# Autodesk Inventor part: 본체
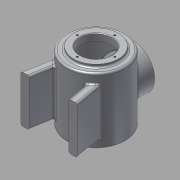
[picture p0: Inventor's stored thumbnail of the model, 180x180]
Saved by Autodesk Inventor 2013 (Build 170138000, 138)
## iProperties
Created: 2015-01
Part Number: 본체
Material: 알루미늄 6061
Document SubType Name: Modeling
Designer: Administrator
Density: 2.71 g/cm^3
Mass: 1058.71 g
Surface Area: 1085.54 cm^2
Volume: 390.668 cm^3
Author: Administrator
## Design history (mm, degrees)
sketch "스케치2"
  geometry: C1 r 50 at (0, 0); 1 further point
  constraints: 1 centre point, 1 coincident
  dimensions: "d0" = 100 diameter of C1
extrude "돌출1" new body sketch "스케치2" distance "d1" = 112; taper "d2" = 0 deg
sketch "스케치3"
  geometry: C1 r 38 at (0, 0); 1 further point
  constraints: 1 centre point, 1 coincident
  dimensions: "d3" = 76 diameter of C1
extrude "돌출2" join sketch "스케치3" distance "d4" = 5; taper "d5" = 0 deg
sketch "스케치4"
  geometry: C1 r 38 at (0, 0); 1 further point
  constraints: 1 centre point, 1 coincident
  dimensions: "d6" = 76 diameter of C1
extrude "돌출3" join sketch "스케치4" distance "d7" = 5; taper "d8" = 0 deg
node "작업 평면2"
  node "작업 평면1"
hole "구멍1" diameter "d25" = 54; stored, may be unused: countersink angle "d29" = 90 deg, drill point angle "d31" = 0 deg; dims "d23" = 10, "d24" = 10, "d26" = 6, "d27" = 4, "d28" = 2, "d30" = 13
hole "구멍2" diameter "d34" = 90; stored, may be unused: countersink angle "d38" = 90 deg, drill point angle "d40" = 0 deg; dims "d32" = 10, "d33" = 10, "d35" = 6, "d36" = 4, "d37" = 2, "d39" = 97
hole "구멍3" diameter "d43" = 54; stored, may be unused: countersink angle "d47" = 90 deg, drill point angle "d49" = 0 deg; dims "d41" = 10, "d42" = 10, "d44" = 6, "d45" = 4, "d46" = 2, "d48" = 12
fillet "모깎기1" dims "d50" = 3
chamfer "모따기1" distance "d51" = 1; stored, may be unused: second distance "d52" = 2, angle "d53" = 45 deg
node "작업 평면3"
sketch "스케치6"
  geometry: L1 (38, 117)-(-38, 117) reference; C1 r 38 at (0, 57); 2 further points
  constraints: 1 centre point, 1 midpoint, 1 vertical alignment
  dimensions: "d58" = 76 diameter of C1; "d59" = 60 distance from line of C1.centre L1
extrude "돌출5" join sketch "스케치6" stored distance "d60" = 80; taper "d61" = 0 deg
hole "구멍4" diameter "d64" = 54; stored, may be unused: countersink angle "d68" = 90 deg, drill point angle "d70" = 0 deg; dims "d62" = 10, "d63" = 10, "d65" = 6, "d66" = 4, "d67" = 2, "d69" = 50
sketch "스케치7"
  geometry: C1 r 38 at (0, 0) reference; 2 further points
  constraints: 1 horizontal alignment
  dimensions: "d71" = 32 distance of C1.centre point (-32, 0)
hole "구멍5" sketch "스케치7" at (-32, 0) diameter "d72" = 3.242; stored, may be unused: countersink angle "d76" = 90 deg, drill point angle "d78" = 118 deg; dims "d73" = 8, "d74" = 4, "d75" = 2, "d77" = 10
sketch "스케치8"
  geometry: C1 r 38 at (0, 0) reference; 2 further points
  constraints: 1 vertical alignment
  dimensions: "d82" = 32 distance of point (0, 0) point (0, 32)
hole "구멍6" sketch "스케치8" at (0, 32) diameter "d83" = 3.242; stored, may be unused: countersink angle "d87" = 90 deg, drill point angle "d89" = 118 deg; dims "d84" = 8, "d85" = 4, "d86" = 2, "d88" = 10
node "작업 평면4"
fillet "모깎기2" dims "d93" = 3
node "작업 평면5"
sketch "스케치9"
  geometry: L1 (-6, 30)-(6, 30); L2 (6, 30)-(6, 84); L3 (6, 84)-(-6, 84); L4 (-6, 84)-(-6, 30); L5 (-38, -5)-(38, -5) reference; 2 further points
  constraints: 8 end point, 2 parallel, 1 horizontal, 1 midpoint, 1 perpendicular, 1 vertical alignment
  dimensions: "d98" = 54 distance between parallel lines of L3 L1; "d100" = 12 distance between parallel lines of L4 L2; "d101" = 35 distance between parallel lines of L1 L5
extrude "돌출6" join sketch "스케치9" stored distance "d102" = 80; taper "d103" = 0 deg
sketch "스케치10"
  geometry: L1 (30, -6)-(30, 6) reference; 3 further points
  constraints: 1 horizontal alignment, 1 midpoint, 1 other
  dimensions: "d104" = 27 distance from line of point (57, 0) L1
feature "엠보싱1" sketch "스케치10" dims "d105" = 0.5, "d106" = 0
chamfer "모따기2" distance "d107" = 1; stored, may be unused: second distance "d108" = 2, angle "d109" = 45 deg
fillet "모깎기6" dims "d110" = 3
fillet "모깎기7" dims "d111" = 3
node "작업 평면6"
sketch "스케치11"
  geometry: L1 (-39.336, -30.865)-(-48, -80); L2 (-27.088, -42.026)-(-33.784, -80); L3 (-48, -80)-(-33.784, -80); L4 (0, 0)-(-50, 0); L5 (0, 0)-(0, -50); A1 r 50 centre (0, 0) between (-39.336, -30.865) and (-27.088, -42.026) reference; 1 further point
  constraints: 10 end point, 4 point on circle, 2 parallel, 1 horizontal, 1 perpendicular
  dimensions: "d117" = 80 distance between parallel lines of L3 L4; "d119" = 14 distance between parallel lines of L2 L1; "d120" = 80 deg angle of L2 L3; "d121" = 48 distance from line of L1.end L5
extrude "돌출7" join sketch "스케치11" stored distance "d122" = 80; taper "d123" = 0 deg
fillet "모깎기8" dims "d124" = 3
fillet "모깎기9" dims "d125" = 3
node "솔리드1"
pattern_circular "원형 패턴1" dims angle "d80" = 360 deg
pattern_circular "원형 패턴2" dims angle "d91" = 360 deg
mirror "대칭2"
mirror "대칭3"
other parameters: "d54" = 62, "d97" = -52
